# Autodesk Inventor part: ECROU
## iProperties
Created: 2011-01
Part Number: ECROU
Document SubType Name: Modeling
Designer: eric
Density: 1 g/cm^3
Mass: 0.51841 g
Surface Area: 5.366 cm^2
Volume: 0.51841 cm^3
Author: eric
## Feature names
1. Base1
